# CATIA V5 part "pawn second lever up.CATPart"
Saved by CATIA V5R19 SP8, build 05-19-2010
Part number: pawn second lever up
Bounding box of the stored display mesh (mm): x 25.189 to 40.189, y 41.4 to 78.4, z 126.989 to 141.613
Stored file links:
  G:\EU_thinkMotion\CFAO_2010\MMS_groupe1\MMS_groupe1\A reprendre\gduval\CFAO kinematic ok\pawn second lever up.CATPart
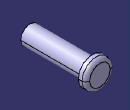
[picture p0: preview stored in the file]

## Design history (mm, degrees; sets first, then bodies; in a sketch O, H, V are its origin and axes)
Body1 (main body)
  Point1: stored without definition
  Plane1: stored without definition
  Sketch1 on Plane1, origin (0, 72.4, 0), H (-1, 0, 0), V (0, 0, 1)
    circle A1 centre (-32.689, 134.301) radius 5
    point P1 (-32.689, 134.301)
    reference projected point E1 (-32.689, 134.301) from Point1
    radius A1 = 5
    coincidence: E1 P1
  Pad1: profile Sketch1, direction (0, -1, 0), length 31, opposite side length 2
  Sketch2 on start face of Pad1, origin (0, 74.4, 0), H (-1, 0, 0), V (0, 0, 1)
    circle A1 centre (-32.689, 134.301) radius 7.5
    reference projected circle E1 centre (-32.689, 134.301) radius 5 from edge [face of Pad1 from Sketch1.A1 | start face of Pad1]
    radius A1 = 7.5
    concentricity: E1 A1
  Pad2: profile Sketch2, direction (0, 1, 0), length 4
  Fillet1: radius 2, on edge [face of Pad2 from Sketch2.A1 | end face of Pad2]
